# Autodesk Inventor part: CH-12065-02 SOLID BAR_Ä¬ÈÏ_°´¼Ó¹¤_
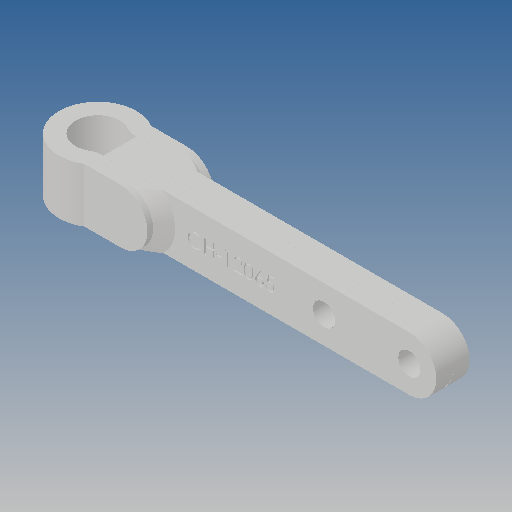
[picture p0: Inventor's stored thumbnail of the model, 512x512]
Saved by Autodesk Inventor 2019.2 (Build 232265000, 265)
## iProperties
Created: 2015-08
Part Number: CH-12065-02 SOLID BAR_Ä¬ÈÏ_°´¼Ó¹¤_
Material: Ogólny
Document SubType Name: Modeling
Designer: CADENGINEERING4
Density: 1 g/cm^3
Appearance: Domyślna
Author: CADENGINEERING4
Revision Number: ÈÎºÎ
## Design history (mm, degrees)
feature "Ô²½Ç1"
feature "Ô²½Çº¸·ì1"
feature "Ô²½Çº¸·ì2"
feature "À­Éì3"
feature "À­Éì6"
node "Bryła1"
node "Bryła2"
node "Bryła3"
node "Bryła4"
node "Bryła5"
